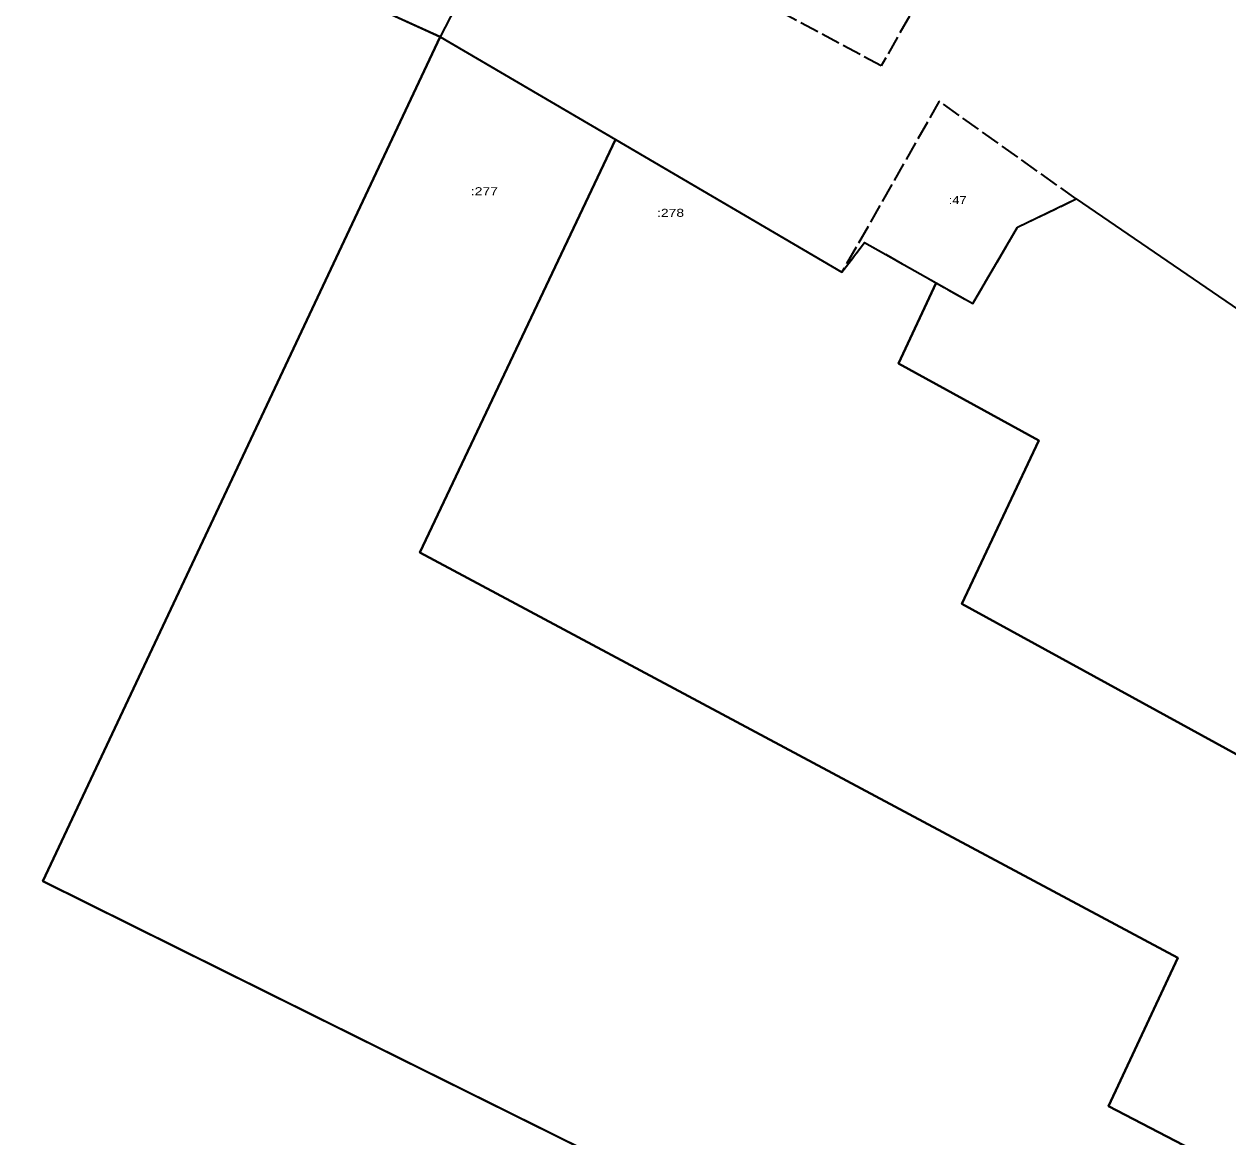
# Model space of a CAD drawing. Extents: x 1178597 to 1179642, y 361068 to 362800.
# Drawn here: x 1179189.1 to 1179414.8, y 362195.6 to 362404.2 of the extents above; entities that cross this region are included whole.
import ezdxf
from ezdxf.enums import TextEntityAlignment as Align

# ---------------------------------------------------------------- set-up
doc = ezdxf.new("R2010")
doc.units = 0
doc.header["$LTSCALE"] = 0.6
doc.linetypes.add('LONG_DASHED', pattern=[7.5, 6, -1.5])
doc.layers.add('2', color=7, linetype='Continuous', lineweight=35)
doc.layers.add('57', color=7, linetype='LONG_DASHED', lineweight=35)

msp = doc.modelspace()

# ---------------------------------------------------------------- linework, layer by layer
at = {"layer": '2'}
msp.add_lwpolyline([(1178937.29, 362676.13), (1179271.17, 362517.67), (1179254.21, 362481.92), (1179295.66, 362457.21), (1179267.04, 362401.8), (1179256.58, 362406.56), (1179277.28, 362446.63), (1179253.05, 362461.08), (1179234.75, 362471.99), (1179241.11, 362485.39), (1179254.2, 362512.95), (1179216, 362531.08), (1179202.92, 362503.52), (1179189.51, 362475.25), (1179174.63, 362443.93)], dxfattribs=at)
for points in [[(1178891.19, 362573.17), (1179267.04, 362401.8), (1179192.55, 362243.52), (1179468.78, 362106.45), (1179321.34, 361904.3), (1179281.73, 361911.69), (1179245.3, 361911.43), (1179204.36, 361904.31), (1179180.02, 361887.37), (1179148.05, 361900.8), (1179128.65, 361905.22), (1179097.75, 361928.91), (1179058.81, 361961.65), (1179007.74, 362014.5), (1178950.38, 362075.56), (1178913.62, 362120.85), (1178888.23, 362168.49), (1178869.92, 362263.16), (1178889.76, 362516.06)], [(1179263.24, 362305.15), (1179405.38, 362229.11), (1179392.38, 362201.34), (1179425.31, 362184.2), (1179490.95, 362151.84), (1179462.41, 362110.11), (1179458.6, 362111.5), (1179192.55, 362243.52), (1179267.04, 362401.8), (1179299.94, 362382.52)], [(1179299.94, 362382.52), (1179342.38, 362357.65), (1179346.64, 362363.23), (1179360.06, 362355.65), (1179352.99, 362340.53), (1179379.32, 362326.13), (1179364.89, 362295.49), (1179450.87, 362248.4), (1179456.38, 362260.05), (1179492.1, 362243.51), (1179477.34, 362221.57), (1179513.35, 362187.89), (1179514.65, 362186.48), (1179490.95, 362151.84), (1179425.31, 362184.2), (1179392.38, 362201.34), (1179405.38, 362229.11), (1179263.24, 362305.15)], [(1179375.31, 362366.1), (1179386.33, 362371.39), (1179517.72, 362281.58), (1179492.1, 362243.51), (1179456.38, 362260.05), (1179450.87, 362248.4), (1179364.89, 362295.49), (1179379.32, 362326.13), (1179352.99, 362340.53), (1179360.06, 362355.65), (1179366.93, 362351.77)]]:
    msp.add_lwpolyline(points, close=True, dxfattribs=at)
at = {"layer": '2', "linetype": 'LONG_DASHED'}
msp.add_lwpolyline([(1179386.33, 362371.39), (1179360.64, 362389.72), (1179342.38, 362357.65), (1179346.64, 362363.23), (1179366.93, 362351.77), (1179375.31, 362366.1)], close=True, dxfattribs=at)
at = {"layer": '57'}
msp.add_lwpolyline([(1179321.94, 362483.47), (1179354.64, 362465.35), (1179345.35, 362450.66), (1179337.63, 362439.31), (1179334.13, 362433.58), (1179334.52, 362433.25), (1179330.74, 362426.96), (1179357.26, 362409.58), (1179349.75, 362396.33), (1179293.1, 362426.82)], close=True, dxfattribs=at)

# ---------------------------------------------------------------- texts
at = {"layer": '2'}
for s, width, p in [(':277', 1.3, (1179275.36, 362372.098)), (':47', 1.2, (1179364.089, 362370.445)), (':278', 1.3, (1179310.259, 362368.045))]:
    msp.add_text(s, height=1.5, dxfattribs=dict(at, width=width)).set_placement(p, align=Align.CENTER)

doc.saveas('drawing.dxf')
